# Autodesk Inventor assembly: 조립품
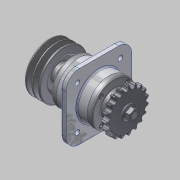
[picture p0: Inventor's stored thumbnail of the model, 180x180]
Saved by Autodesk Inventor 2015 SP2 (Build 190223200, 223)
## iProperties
Created: 2015-07
Part Number: 조립품
Document SubType Name: Assembly
Designer: AMC
Author: AMC
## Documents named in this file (12)
- C:\Users\AMC\Desktop\450735V1016\조립품.iam
- C:\Users\AMC\Desktop\450735V1016\본체.ipt
- C:\Users\AMC\Desktop\450735V1016\2-커버.ipt
- C:\Users\AMC\Desktop\450735V1016\3-축.ipt
- C:\Users\AMC\Desktop\450735V1016\4-V벨트풀리.ipt
- C:\Users\AMC\Desktop\450735V1016\5-체인 스프로킷.ipt
- C:\Users\AMC\Desktop\450735V1016\6-베어링 6206.ipt
- C:\Users\AMC\Desktop\450735V1016\7-부시.ipt
- C:\Users\AMC\Desktop\450735V1016\8-오일실 30x42.ipt
- C:\Users\AMC\Desktop\450735V1016\9-M16-너트.ipt
- C:\Users\AMC\Desktop\450735V1016\10-M6.ipt
- C:\Users\AMC\Desktop\450735V1016\11-키 6x6.ipt
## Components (22 placed, 10 different names)
1. 2-커버:1
2. 3-축:1
3. 4-V벨트풀리:1 — 각도:1
4. 5-체인 스프로킷:1 — 각도:2
5. 6-베어링 6206:1
6. 7-부시:1
7. 8-8-오일실 30x42:1
8. 9-M16 너트:1
9. 11-키 6x6:1 — 각도:2
10. 11-키 6x6:2 — 각도:1
11. 6-베어링 6206:2
12. 2-커버:2
13. 8-8-오일실 30x42:2
14. 9-M16 너트:2
15. 10-M6:1
16. 10-M6:2
17. 10-M6:3
18. 10-M6:4
19. 10-M6:5
20. 10-M6:6
21. 10-M6:7
22. 10-M6:8
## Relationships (2: Angle 2)
- 각도:1 [Angle]: 4-V벨트풀리:1 ↔ 11-키 6x6:2
- 각도:2 [Angle]: 5-체인 스프로킷:1 ↔ 11-키 6x6:1
